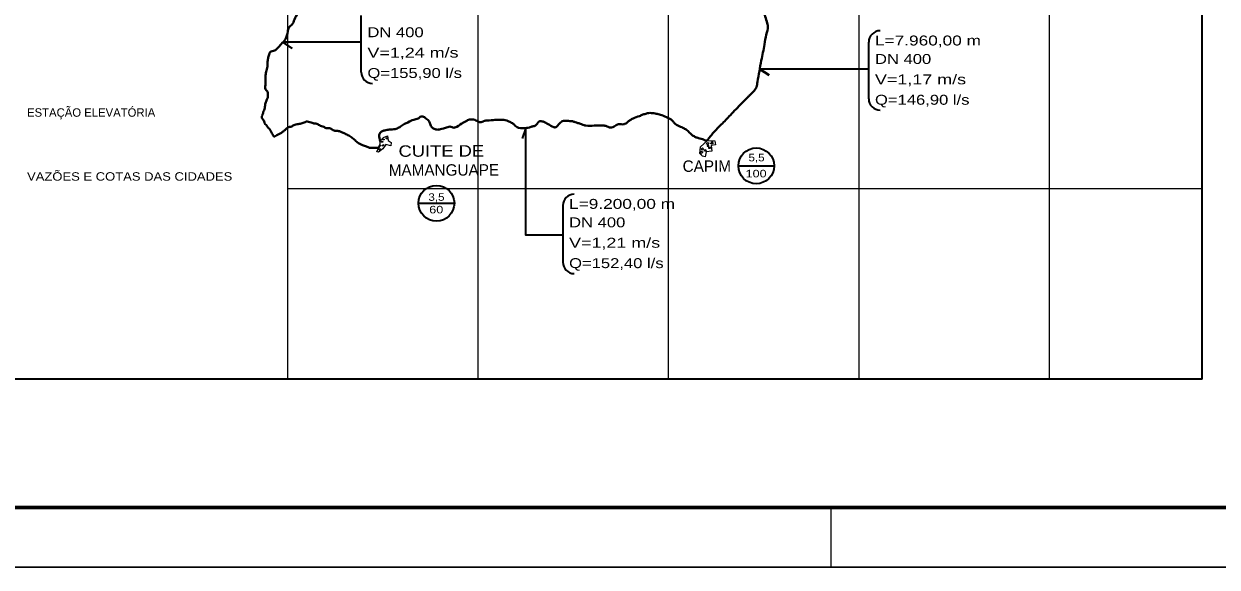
# Model space of a CAD drawing. Extents: x 0 to 1772, y 0 to 1188.
# Drawn here: x 781.9 to 1181, y -0.1 to 181.7 of the extents above; entities that cross this region are included whole.
import ezdxf
from ezdxf.enums import TextEntityAlignment as Align

# ---------------------------------------------------------------- set-up
doc = ezdxf.new("R2010")
doc.units = 0
doc.header["$LTSCALE"] = 1.3
doc.linetypes.add('DOT_DASHED', pattern=[7.7, 5, -1.2, 0.3, -1.2])
for name, color, linetype, lineweight in [('1', 7, 'DOT_DASHED', 13), ('6', 7, 'Continuous', 40), ('63', 7, 'Continuous', 25), ('8', 7, 'Continuous', 35), ('9', 7, 'Continuous', 40)]:
    doc.layers.add(name, color=color, linetype=linetype, lineweight=lineweight)

msp = doc.modelspace()

# ---------------------------------------------------------------- linework, layer by layer
at = {"layer": '1', "linetype": 'Continuous'}
for points in [[(899.898, 138.885), (901.045, 141.134), (901.009, 142.433), (902.111, 143.607), (903.535, 144.14), (903.683, 142.682), (904.727, 141.931), (904.602, 140.84), (902.967, 141.3), (901.866, 139.886), (900.427, 138.71)], [(900.794, 139.433), (900.633, 139.593), (901.001, 139.963), (901.161, 139.803)], [(901.394, 142.065), (901.394, 142.292), (901.89, 142.293), (901.891, 142.067)], [(901.734, 140.847), (901.941, 141.329), (902.239, 141.201), (902.032, 140.72)], [(901.857, 142.852), (901.856, 143.079), (902.385, 143.081), (902.385, 142.854)], [(902.993, 143.225), (903.184, 143.658), (903.618, 143.467), (903.427, 143.034)], [(1008.387, 139.777), (1008.855, 140.181), (1009.169, 139.817), (1008.701, 139.412)], [(1010.208, 141.435), (1010.367, 142.014), (1010.945, 141.854), (1010.786, 141.276)], [(1010.371, 140.696), (1010.921, 140.698), (1010.921, 140.953), (1010.37, 140.952)], [(1010.977, 139.932), (1010.976, 140.389), (1011.433, 140.39), (1011.434, 139.933)], [(1011.604, 141.533), (1011.603, 141.749), (1012.301, 141.751), (1012.302, 141.536)], [(1011.817, 141.937), (1011.817, 142.152), (1012.34, 142.154), (1012.341, 141.939)], [(1008.229, 138.499), (1008.389, 139.01), (1008.9, 138.851), (1008.74, 138.34)], [(1009.449, 139.229), (1009.676, 139.606), (1010.053, 139.378), (1009.826, 139.001)]]:
    msp.add_lwpolyline(points, close=True, dxfattribs=at)
msp.add_lwpolyline([(1008.648, 137.89), (1007.894, 138.277), (1008.203, 140.465), (1010.551, 142.683), (1013.004, 142.496), (1013.153, 141.136), (1011.793, 140.986), (1012.009, 139.019), (1010.042, 138.802), (1009.718, 137.213), (1008.795, 137.401), (1007.894, 138.277)], dxfattribs=at)
at = {"layer": '6'}
for p, q in [((965.316, 149.051), (965.14, 149.055)), ((900.64, 143.948), (901.009, 142.433))]:
    msp.add_line(p, q, dxfattribs=at)
for points in [[(876.637, 222.852), (875.879, 220.627), (876.25, 219.965), (877.145, 219.552), (877.678, 219.294), (879.095, 217.833), (879.992, 216.745), (880.709, 215.45), (881.231, 214.31), (881.985, 213.508), (882.857, 212.329), (883.743, 210.775), (884.108, 209.829), (883.839, 209.05), (883.18, 208.14), (882.78, 207.632), (882.201, 206.907), (881.427, 206.068), (880.572, 204.971), (879.881, 203.804), (879.179, 202.742), (878.641, 201.657), (878.021, 200.666), (877.459, 199.852), (877.46, 199.44), (877.616, 198.417), (877.771, 197.652), (878.474, 195.316), (879.593, 193.258), (879.123, 192.143), (876.934, 189.239), (874.881, 187.004), (873.578, 185.469), (872.361, 183.097), (871.448, 181.312), (870.477, 180.362), (870.147, 179.079), (869.32, 176.514), (867.906, 174.866), (866.744, 173.505), (865.68, 172.701), (864.328, 172.286), (863.879, 171.443), (863.534, 170.128), (863.333, 168.711), (863.337, 167.364), (862.912, 165.63), (862.65, 164.11), (862.655, 162.489), (862.659, 161.141), (862.663, 159.793), (863.239, 159.164), (863.467, 158.18), (863.47, 157.276), (863.154, 156.291), (862.679, 155.135), (862.398, 153.523), (861.935, 152.014), (861.618, 151.053), (861.414, 150.458), (861.69, 149.831), (862.321, 148.667), (862.322, 148.461), (862.917, 147.857), (863.318, 147.242), (863.857, 146.603), (864.308, 145.961), (864.831, 145.131), (865.23, 144.326), (865.442, 144.004), (866.185, 144.18), (866.68, 144.553), (867.571, 144.978), (868.376, 145.477), (869.142, 146.075), (869.884, 146.76), (870.738, 147.184), (871.11, 147.185), (871.757, 147.571), (873.27, 148.065), (874.608, 148.337), (875.9, 148.807), (876.656, 148.985), (877.507, 148.719), (878.311, 148.5)], [(1026.288, 195.944), (1027.862, 190.814), (1028.772, 187.696), (1029.831, 184.1), (1030.476, 181.92), (1030.672, 181.139), (1030.727, 180.863), (1030.173, 177.991), (1029.567, 174.805), (1028.509, 169.395), (1027.251, 162.313), (1026.888, 160.509), (1026.803, 160.245), (1026.315, 159.545), (1025.404, 158.587), (1024.533, 157.71), (1023.812, 156.941), (1023.307, 156.415), (1021.965, 155.073), (1018.167, 151.123), (1015.097, 147.953), (1012.556, 145.333), (1011.612, 144.176), (1010.783, 143.075), (1010.549, 142.744), (1009.148, 142.985)], [(996.752, 150.471), (994.758, 151.268), (993.364, 151.583), (991.815, 151.825), (990.738, 151.822), (989.549, 151.492), (988.331, 151.051), (987.774, 150.815), (985.602, 149.979), (984.648, 149.438), (983.914, 148.925), (983.401, 148.473), (982.882, 148.17), (982.547, 148.063), (980.781, 148.057), (979.282, 147.271), (978.439, 146.931), (977.699, 146.999), (976.777, 147.393), (975.607, 147.64), (972.603, 147.631), (969.815, 147.622), (969.23, 147.759), (968.346, 148.094), (967.131, 148.478), (966.306, 148.743), (965.316, 149.051)], [(878.311, 148.5), (878.849, 148.329), (879.544, 148.331), (880.743, 147.728), (882.149, 147.184), (883.244, 146.714), (884.131, 146.717), (885.019, 146.29), (886.203, 145.835), (886.868, 145.837), (887.871, 145.511), (888.943, 145.062), (890.208, 144.459), (891.513, 143.663), (892.65, 142.698), (893.775, 141.759), (894.627, 141.297), (895.137, 141.081), (896.461, 140.648), (897.512, 140.188), (898.998, 140.192), (900.345, 140.196), (901.045, 141.134)], [(919.477, 146.417), (918.639, 146.719), (918.152, 147.204), (917.877, 147.864), (917.407, 148.975), (916.336, 150.027), (915.291, 150.661), (914.18, 150.328), (913.781, 149.992), (912.992, 149.73), (912.235, 149.566), (910.324, 148.704), (909.215, 148.163), (907.849, 147.287), (906.729, 146.681), (906.049, 146.452), (904.066, 146.275), (902.574, 145.987), (901.525, 145.618), (900.88, 144.968), (900.64, 143.946)], [(965.14, 149.055), (963.683, 149.197), (961.922, 149.059), (960.906, 148.19), (959.967, 147.193), (959.626, 146.987), (959.499, 146.987), (959.068, 147.134), (957.172, 148.088), (955.6, 148.935), (954.16, 148.931), (953.337, 147.999), (953.02, 147.686), (952.485, 147.467), (951.514, 147.195), (950.947, 147.006), (949.977, 146.876), (947.266, 146.868), (946.802, 147.053), (946.209, 147.569), (945.555, 148.196), (944.905, 148.592), (943.845, 149.14), (941.881, 149.547), (936.908, 149.331), (935.774, 149.181), (934.43, 148.739), (934.048, 148.849), (933.072, 149.314), (931.293, 149.696), (929.969, 149.239), (928.305, 148.32), (926.026, 146.979), (925.704, 146.902), (925.056, 147.1), (924.353, 147.274), (922.906, 146.84), (922.182, 146.623), (921.212, 146.369), (919.96, 146.281), (919.411, 146.431)], [(1009.215, 142.984), (1007.508, 143.417), (1006.496, 143.773), (1005.533, 144.326), (1004.405, 145.354), (1003.352, 146.254), (1002.308, 146.859), (1001.457, 147.235), (1000.539, 147.698), (999.81, 148.127), (999.284, 148.622), (998.502, 149.49), (997.675, 150.014), (996.806, 150.437)]]:
    msp.add_spline(points, degree=3, dxfattribs=at)
at = {"layer": '63', "lineweight": 13}
for p, q in [((870.095, 62.735), (870.095, 419.523)), ((933.807, 62.735), (933.807, 419.523)), ((997.519, 62.735), (997.519, 419.523)), ((1061.231, 62.735), (1061.231, 419.523)), ((1124.943, 62.735), (1124.943, 419.523)), ((1175.913, 126.447), (870.095, 126.447))]:
    msp.add_line(p, q, dxfattribs=at)
at = {"layer": '63', "lineweight": 35}
for p, q in [((1175.913, 62.735), (1175.913, 419.523)), ((1051.833, 19.873), (1401.833, 19.873))]:
    msp.add_line(p, q, dxfattribs=at)
at = {"layer": '63'}
msp.add_line((1051.833, -0.127), (1051.833, 19.873), dxfattribs=at)
for points in [[(-0.167, -0.127), (1771.833, -0.127), (1771.833, 1187.873)], [(-0.167, -0.127), (1771.833, -0.127), (-0.167, -0.127)]]:
    msp.add_lwpolyline(points, dxfattribs=at)
at = {"layer": '63', "lineweight": 60}
msp.add_lwpolyline([(49.833, 1167.873), (1751.833, 1167.873), (1751.833, 19.873), (49.833, 19.873)], close=True, dxfattribs=at)
at = {"layer": '63', "lineweight": 35}
msp.add_lwpolyline([(1175.913, 62.735), (487.822, 62.735), (487.822, 419.523)], dxfattribs=at)
at = {"layer": '8'}
for p, q in [((894.671, 165.528), (894.671, 184.484)), ((894.671, 175.485), (868.442, 175.485)), ((1064.433, 156.579), (1064.433, 175.534)), ((1064.433, 166.536), (1027.988, 166.536)), ((962.117, 120.869), (962.117, 101.914))]:
    msp.add_line(p, q, dxfattribs=at)
at = {"layer": '8', "lineweight": 40}
for p, q in [((868.442, 175.485), (871.614, 173.422)), ((1027.988, 166.536), (1031.161, 164.472))]:
    msp.add_line(p, q, dxfattribs=at)
at = {"layer": '8'}
msp.add_lwpolyline([(962.117, 110.912), (949.767, 110.912), (949.767, 146.838), (948.501, 143.272)], dxfattribs=at)
for centre, start, end in [((1068.255, 175.534), 90, 180), ((1068.255, 175.534), 90, 180), ((1068.255, 175.534), 90, 180), ((898.494, 165.528), 180, 270), ((1068.255, 156.579), 180, 270), ((965.939, 120.869), 90, 180), ((965.939, 101.914), 180, 270), ((965.939, 101.914), 180, 270), ((965.939, 101.914), 180, 270)]:
    msp.add_arc(centre, 3.823, start, end, dxfattribs=at)
at = {"layer": '9', "lineweight": 35}
for p, q in [((1020.843, 134.15), (1032.813, 134.15)), ((913.866, 121.626), (925.837, 121.626))]:
    msp.add_line(p, q, dxfattribs=at)
for centre in [(1026.828, 134.15), (919.852, 121.626)]:
    msp.add_circle(centre, 5.985, dxfattribs=at)

# ---------------------------------------------------------------- texts
at = {"layer": '63'}
msp.add_text('ESTAÇÃO ELEVATÓRIA', height=2.829, dxfattribs=at).set_placement((782.917, 150.579))
at = {"layer": '63', "width": 1.15}
msp.add_text('VAZÕES E COTAS DAS CIDADES', height=2.829, dxfattribs=at).set_placement((782.917, 129.178))
at = {"layer": '8'}
for s, width, p in [('DN 400', 1.25, (896.768, 177.191)), ('L=7.960,00 m', 1.3, (1066.53, 174.421)), ('V=1,24 m/s', 1.35, (896.768, 170.368)), ('DN 400', 1.25, (1066.53, 168.241)), ('Q=155,90 l/s', 1.25, (896.768, 163.544)), ('V=1,17 m/s', 1.35, (1066.53, 161.418)), ('Q=146,90 l/s', 1.25, (1066.53, 154.594)), ('L=9.200,00 m', 1.3, (964.214, 119.756)), ('DN 400', 1.25, (964.214, 113.576)), ('V=1,21 m/s', 1.35, (964.214, 106.753)), ('Q=152,40 l/s', 1.25, (964.214, 99.929))]:
    msp.add_text(s, height=3.319, dxfattribs=dict(at, width=width)).set_placement(p)
at = {"layer": '9'}
for s, height, width, p in [('CUITE DE ', 3.823, 1.2, (922.337, 137.218)), ('5,5', 2.52, 1.15, (1026.912, 135.658)), ('100', 2.52, 1.25, (1026.764, 130.3)), ('3,5', 2.52, 1.15, (919.861, 122.446)), ('60', 2.52, 1.25, (919.787, 118.243))]:
    msp.add_text(s, height=height, rotation=0.17, dxfattribs=dict(at, width=width)).set_placement(p, align=Align.CENTER)
msp.add_text('CAPIM', height=3.823, rotation=0.17, dxfattribs=at).set_placement((1002.2, 132.122))
msp.add_text('MAMANGUAPE', height=3.823, rotation=0.17, dxfattribs=at).set_placement((922.356, 130.847), align=Align.CENTER)

doc.saveas('drawing.dxf')
